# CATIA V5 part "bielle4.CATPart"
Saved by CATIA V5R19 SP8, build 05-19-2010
Part number: Pièce4
Bounding box of the stored display mesh (mm): x -20 to 0, y -12.31 to 393.31, z -12.5 to 12.5
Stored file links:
  G:\EU_thinkMotion\CFAO_2010\SIL_groupe1\SIL_groupe1\A reprendre\lalpha\lalpha\Alpha.mécanisme\bielle4.CATPart
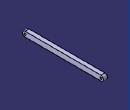
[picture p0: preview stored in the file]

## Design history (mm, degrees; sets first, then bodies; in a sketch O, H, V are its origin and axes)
Body1 (main body)
  Line1: stored without definition
  Line2: stored without definition
  Sketch1 on Line1, origin (0, 0, 0), H (0, 1, 0), V (0, 0, 1)
    point P1 (0, 12.5)
    line L1 (0, 12.5) -> (381, 12.5)
    line L2 (381, -12.5) -> (0, -12.5)
    arc A1 centre (0, 0) radius 12.5 from (0, 12.5) to (0, -12.5) ccw
    arc A2 centre (381, 0) radius 12.5 from (381, -12.5) to (381, 12.5) ccw
    circle A3 centre (0, 0) radius 5
    circle A4 centre (381, 0) radius 5
    coincidence: P1 V
    horizontal: L1 H, L2 H
    tangency: A1 L1, A2 L1
  Pad1: profile Sketch1, direction (-1, 0, 0), length 20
